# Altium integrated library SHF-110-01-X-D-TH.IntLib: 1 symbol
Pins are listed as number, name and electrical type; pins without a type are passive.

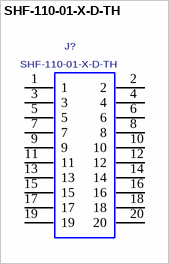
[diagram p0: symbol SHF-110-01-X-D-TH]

## SHF-110-01-X-D-TH
designator J?
0.05"X0.05" SHROUDED TERMINAL STRIP.; MANUFACTURER: SAMTEC
footprint SHF-110-01-X-D-TH
pins: 1, 2, 3, 4, 5, 6, 7, 8, 9, 10, 11, 12, 13, 14, 15, 16, 17, 18, 19, 20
